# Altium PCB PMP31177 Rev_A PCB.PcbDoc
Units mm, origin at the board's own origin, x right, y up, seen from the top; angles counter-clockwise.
Board outline 38.73 x 19.68 mm, 4 copper layers (Top Layer, Layer 1, Layer 2, Bottom Layer), stack 1.787 mm thick; 35 components, 19 nets, 80 pads, 40 vias.
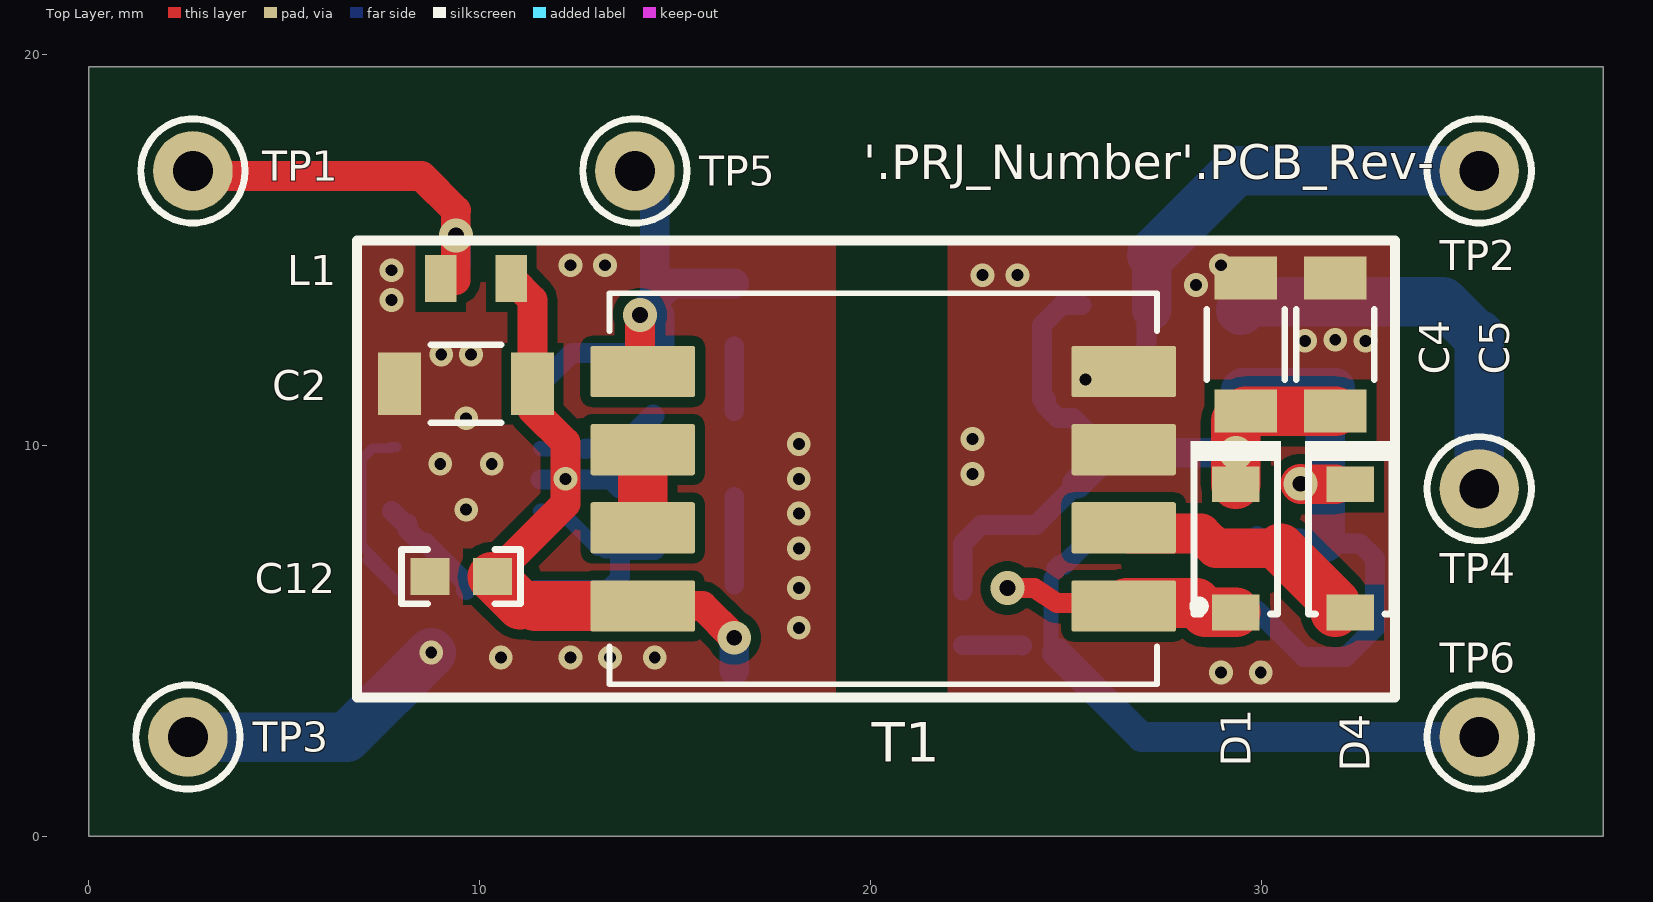
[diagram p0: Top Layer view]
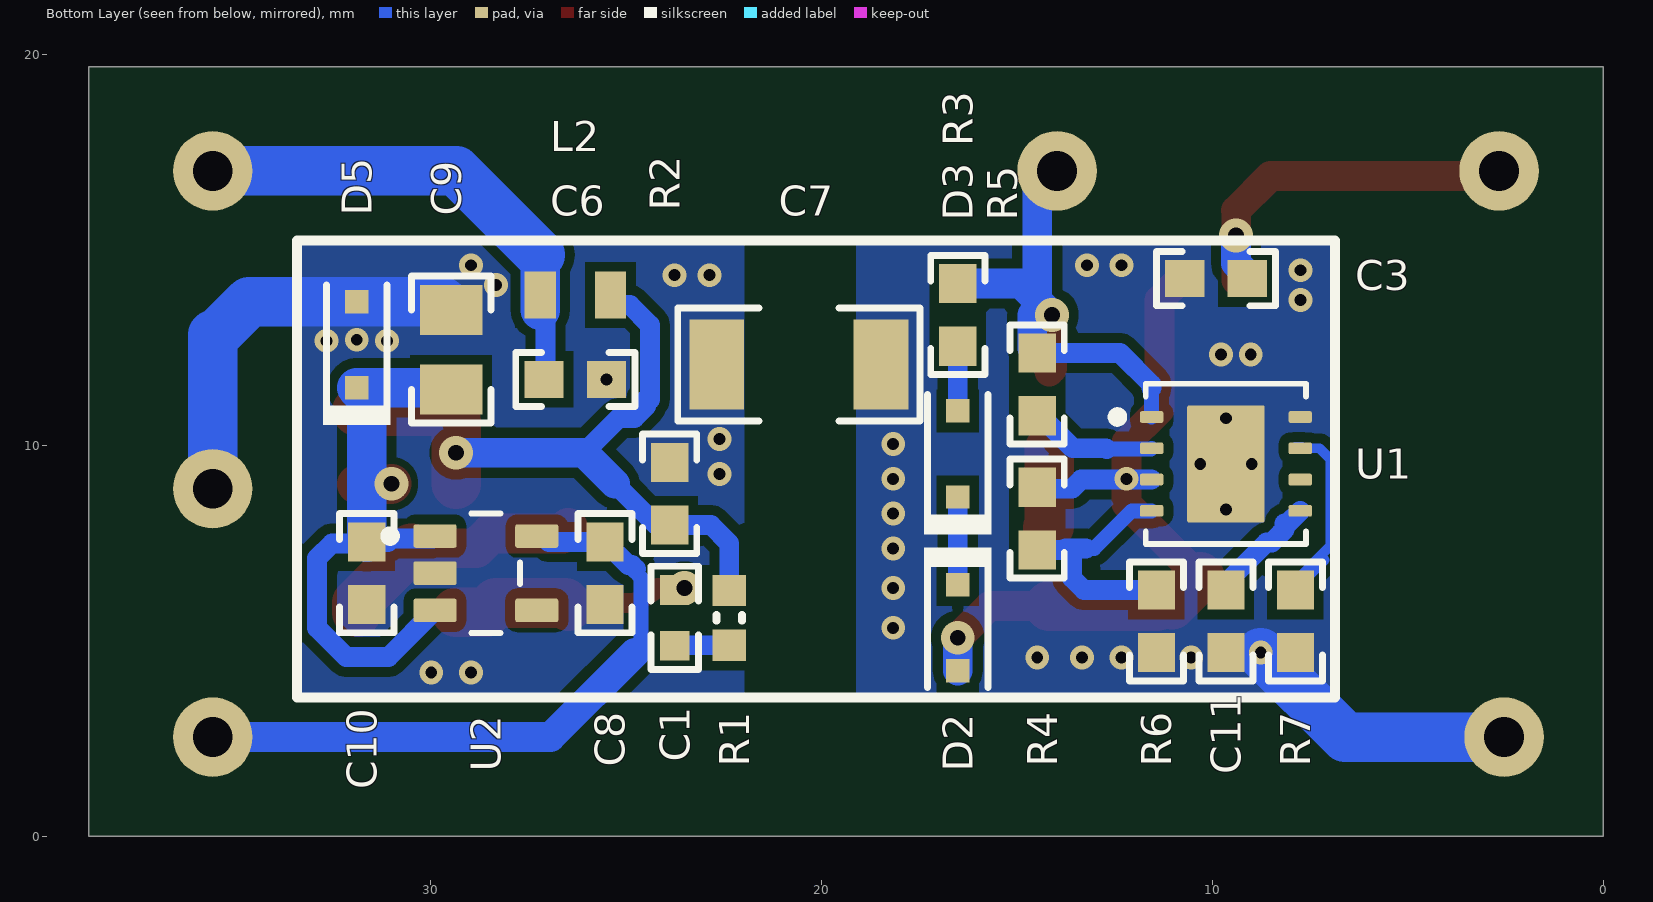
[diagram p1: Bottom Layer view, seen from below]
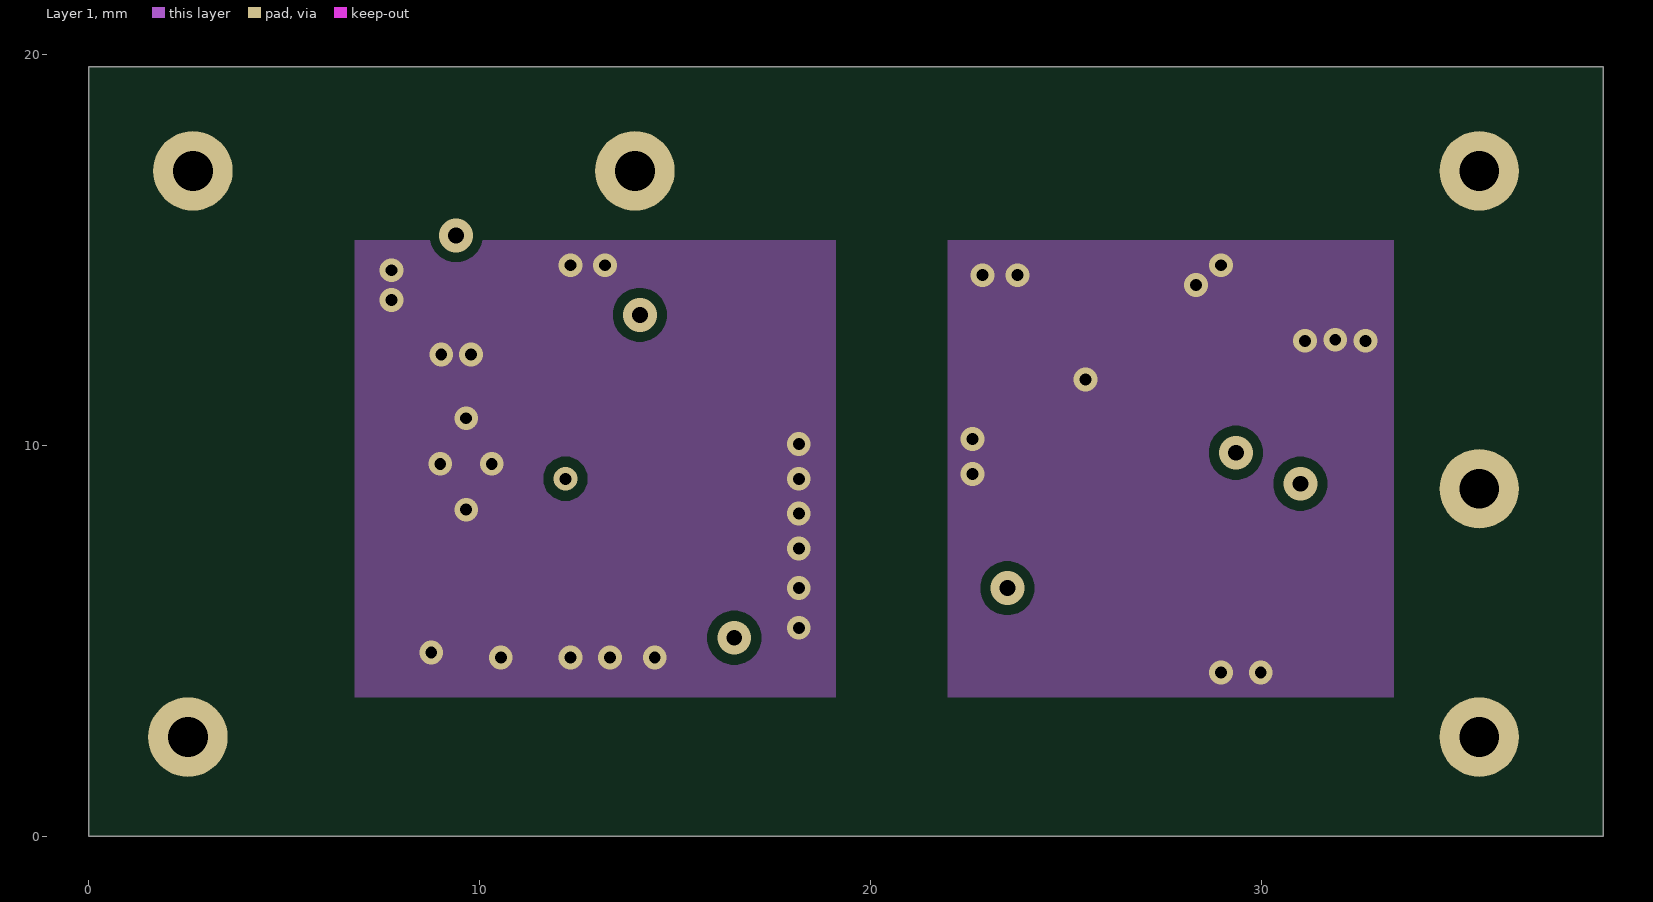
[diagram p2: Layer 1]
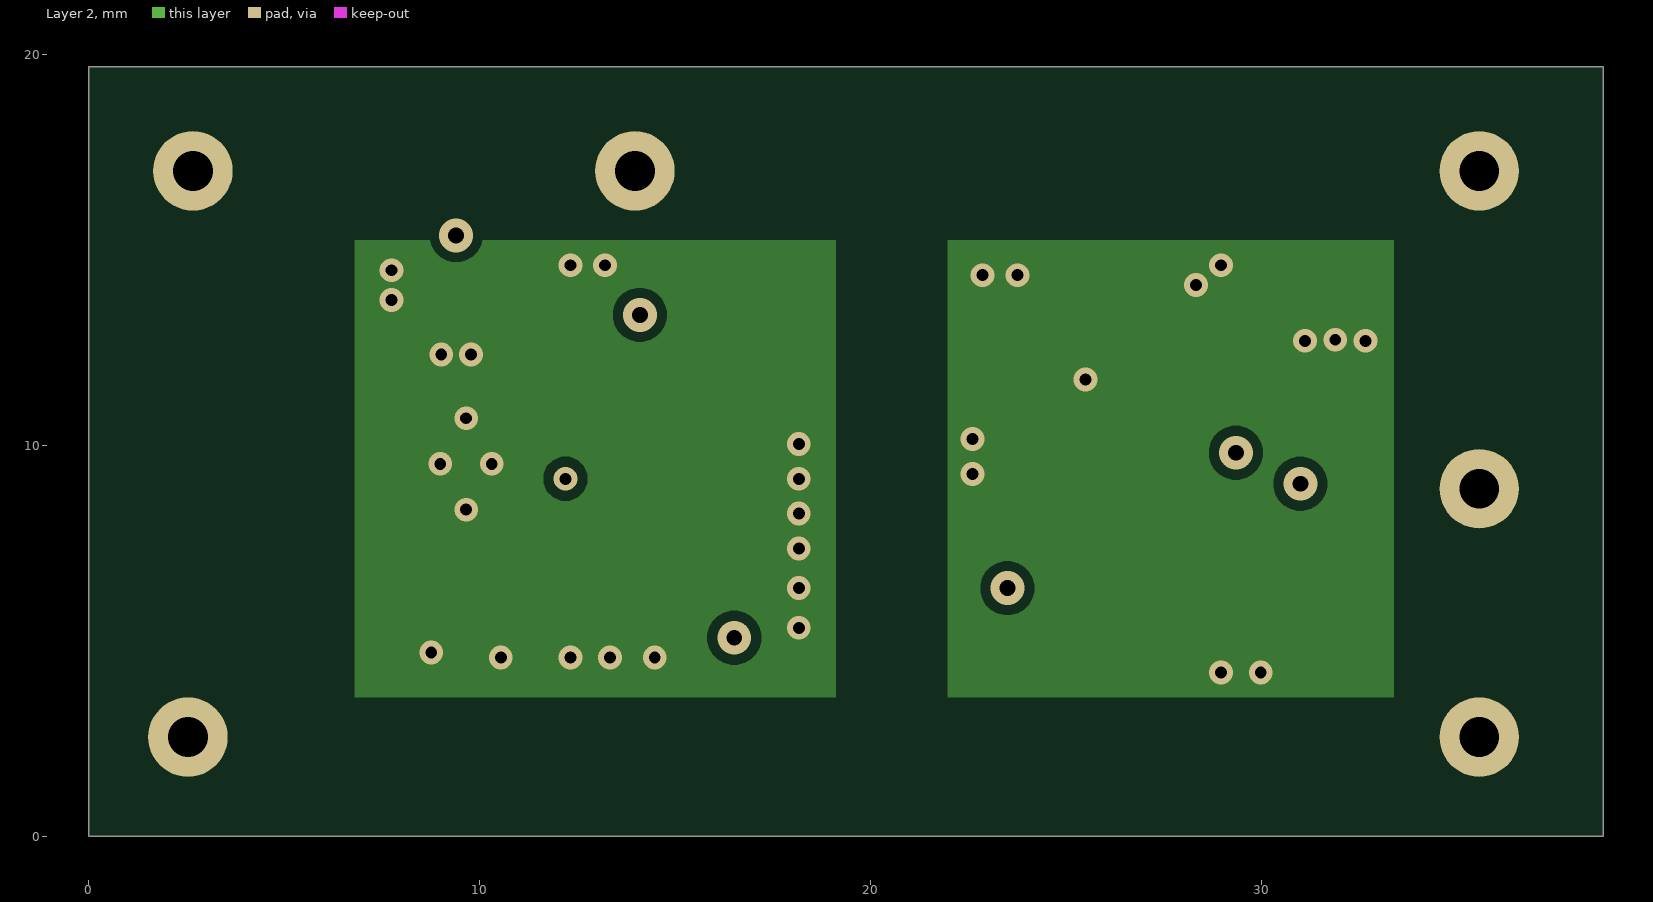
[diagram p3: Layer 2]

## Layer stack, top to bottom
Top Solder: solder mask 0.0102, Solder Resist, Dk 3.5
Top Layer: signal copper 0.0356
Dielectric 1: prepreg 0.0711, PP-006, Dk 4.1
Layer 1: signal copper 0.035
Dielectric1: core 1.5037, FR-4, Dk 4.8
Layer 2: signal copper 0.035
Dielectric 2: prepreg 0.0711, PP-006, Dk 4.1
Bottom Layer: signal copper 0.0356
Bottom Solder: solder mask 0.0102, Solder Resist, Dk 3.5

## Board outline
0,0 0,19.685 38.735,19.685 38.735,0

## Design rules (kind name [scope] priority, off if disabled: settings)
AcuteAngle [All] p1: minimum=4.50000000000000E+0001 checktracksonly=FALSE
AssemblyTestPointUsage [All] p1: valid=2
BoardOutlineClearance BoardOutlineClearance_MountingHoles [OnCopper and InComponentClass('Mounting Holes')] p1: gap=1.016 ignorepadtopadclearanceinfootprint=FALSE
BoardOutlineClearance BoardOutlineClearance_Poly [OnCopper and IsPoly] p2: gap=0.635 ignorepadtopadclearanceinfootprint=FALSE
BoardOutlineClearance [OnCopper and Not InComponentClass('Logo') and not InComponentClass('FiducialMark') and not InRegion(1000,500,4000,800) and not InPoly] p3: gap=1.905 ignorepadtopadclearanceinfootprint=FALSE
Clearance Clearance_1 [All] p1: gap=0.254 ignorepadtopadclearanceinfootprint=FALSE except(0: Arc-Hole Track-Hole SMDPad-Hole THPad-Hole Via-Hole Fill-Hole Poly-Hole Region-Hole Text-Hole)
Clearance Clearance_Keepouts [((IsTrack Or IsArc) And Not InPoly) And IsFree and IsKeepOut vs ((IsTrack Or IsArc) And Not InPoly) And IsFree and IsKeepOut] p2: gap=0 ignorepadtopadclearanceinfootprint=FALSE
Clearance Clearance_Poly [InPolygon] p3: gap=0.254 ignorepadtopadclearanceinfootprint=FALSE
Clearance Clearance_FiducialMark [IsKeepOut and InComponentClass('FiducialMark') vs IsPad and InComponentClass('FiducialMark')] p4: gap=0 ignorepadtopadclearanceinfootprint=FALSE
Clearance [All] p5: gap=0.254 ignorepadtopadclearanceinfootprint=FALSE
ComponentClearance ComponentClearance_MountingHoles_FiducialMarks [InComponentClass('Mounting Holes') vs InComponentClass('FiducialMark')] p1: gap=1.27 collisioncheckmode=3 verticalgap=0.254 showdistances=FALSE
ComponentClearance ComponentClearance_Shunt [InComponentClass('Header') vs InComponentClass('Shunt')] p2: gap=0 collisioncheckmode=3 verticalgap=0 showdistances=FALSE
ComponentClearance ComponentClearance_Logo [InComponentClass('Logo')] p3: gap=1.27 collisioncheckmode=3 verticalgap=0.254 showdistances=FALSE
ComponentClearance ComponentClearance_ScrewToNut [(HasFootprint('NY PMS 440 0025 PH')) vs (HasFootprint('Keystone_1902C'))] p4: gap=0.127 collisioncheckmode=3 verticalgap=0.254 showdistances=FALSE
ComponentClearance ComponentClearance_MountingHoles [InComponentClass('Mounting Holes')] p5: gap=6.35 collisioncheckmode=3 verticalgap=2540 showdistances=FALSE
ComponentClearance ComponentClearance_SmallPassives [HasFootprint('0201*') or HasFootprint('0402*') or HasFootprint('0508') or HasFootprint('0603*') or HasFootprint('0612') or HasFootprint('0805*') or HasFootprint('0815*') or HasFootprint('0830*') or HasFootprint('1206*') or HasFootprint('1210*') or HasFootprint('1808*') or HasFootprint('1812*') or HasFootprint('1825*') or HasFootprint('2010*') or HasFootprint('2220*') or HasFootprint('2225*') or HasFootprint('2512*') or HasFootprint('2728*') or HasFootprint('3518*') vs HasFootprint('0201*') or HasFootprint('0402*') or HasFootprint('0508') or HasFootprint('0603*') or HasFootprint('0612') or HasFootprint('0805*') or HasFootprint('0815*') or HasFootprint('0830*') or HasFootprint('1206*') or HasFootprint('1210*') or HasFootprint('1808*') or HasFootprint('1812*') or HasFootprint('1825*') or HasFootprint('2010*') or HasFootprint('2220*') or HasFootprint('2225*') or HasFootprint('2512*') or HasFootprint('2728*') or HasFootprint('3518*')] p6: gap=0.38 collisioncheckmode=3 verticalgap=0.254 showdistances=FALSE
ComponentClearance ComponentClearance_THtoSMT [IsThruComponent vs IsSMTComponent] p7: gap=1.016 collisioncheckmode=3 verticalgap=0.762 showdistances=FALSE
ComponentClearance ComponentClearance_THtoTH [IsThruComponent vs IsThruComponent] p8: gap=0.762 collisioncheckmode=3 verticalgap=0.762 showdistances=FALSE
ComponentClearance [All] p9: gap=0.762 collisioncheckmode=3 verticalgap=0.254 showdistances=FALSE
DiffPairsRouting [All] p1: maxlimit=2.54 minlimit=0.254 mostfreqgap=0.254 toplayer_minwidth=0.381 toplayer_maxwidth=0.381 toplayer_prefwidth=0.381 midlayer1_minwidth=0.381 midlayer1_maxwidth=0.381 midlayer1_prefwidth=0.381 midlayer2_minwidth=0.381 midlayer2_maxwidth=0.381 midlayer2_prefwidth=0.381 bottomlayer_minwidth=0.381 bottomlayer_maxwidth=0.381 bottomlayer_prefwidth=0.381 maxuncoupledlength=25.4
FabricationTestPointUsage TestPointUsage [All] p1: valid=2 allowmultiple=FALSE
FabricationTestpoint Testpoint [All] p1: side=3 testpointundercomponent=TRUE minsize=1.016 maxsize=2.54 preferedsize=1.524 minholesize=0 maxholesize=1.016 preferedholesize=0.813 testpointgrid=0.025 allowsidetop=TRUE allowsidebottom=TRUE usegrid=TRUE gridtolerance=0
FanoutControl Fanout_LCC [IsLCC] p1: bgadir=Out bgaviamode=Centered fanoutstyle=Auto fanoutdirection=Alternating viagrid=0.025 // Fanout_LCC (Default Rule)
FanoutControl Fanout_BGA [IsBGA] p2: bgadir=Out bgaviamode=Centered fanoutstyle=Auto fanoutdirection=Alternating viagrid=0.025 // Fanout_BGA (Default Rule)
FanoutControl Fanout_Default [All] p4: bgadir=Out bgaviamode=Centered fanoutstyle=Auto fanoutdirection=Alternating viagrid=0.025 // Fanout_Default (Default Rule)
FanoutControl Fanout_Small [(CompPinCount < 5)] p5: bgadir=Out bgaviamode=Centered fanoutstyle=Auto fanoutdirection=OutThenIn viagrid=0.025 // Fanout_Small (Default Rule)
HoleSize [All] p1: absolutevalues=TRUE maxlimit=6.375 minlimit=0.3 maxpercent=80.000 minpercent=20.000
MinimumAnnularRing MinimumAnnularRing_ThermalPadVias [IsVia and InAnyComponent] p1: minimumring=0.15
MinimumAnnularRing [All] p2: minimumring=0.152
MinimumSolderMaskSliver MinimumSolderMaskSliver_Logo [InComponentClass('Logo') vs InComponentClass('Logo')] p1: minsoldermaskwidth=0.018
MinimumSolderMaskSliver [All] p2: minsoldermaskwidth=0.1
PlaneConnect [All] p1: planeconnectstyle=Relief reliefexpansion=0.254 reliefentries=4 reliefconductorwidth=0.254 reliefairgap=0.254
PolygonConnect PolygonConnect_8 [All vs IsNamedPolygon('BOTTOM_LAYER_GND_P004')] p1: connectstyle=Direct reliefconductorwidth=0.254 reliefentries=4 polygonreliefangle="90 Angle" airgapwidth=0.254
PolygonConnect PolygonConnect_7 [All vs IsNamedPolygon('LAYER_2_GND_P007')] p2: connectstyle=Direct reliefconductorwidth=0.254 reliefentries=4 polygonreliefangle="90 Angle" airgapwidth=0.254
PolygonConnect PolygonConnect_6 [All vs IsNamedPolygon('LAYER_1_GND_P006')] p3: connectstyle=Direct reliefconductorwidth=0.254 reliefentries=4 polygonreliefangle="90 Angle" airgapwidth=0.254
PolygonConnect PolygonConnect_5 [All vs IsNamedPolygon('TOP_LAYER_GND_P005')] p4: connectstyle=Direct reliefconductorwidth=0.254 reliefentries=4 polygonreliefangle="90 Angle" airgapwidth=0.254
PolygonConnect PolygonConnect_4 [All vs IsNamedPolygon('LAYER_2_SGND_P003')] p5: connectstyle=Direct reliefconductorwidth=0.254 reliefentries=4 polygonreliefangle="90 Angle" airgapwidth=0.254
PolygonConnect PolygonConnect_3 [All vs IsNamedPolygon('LAYER_1_SGND_P002')] p6: connectstyle=Direct reliefconductorwidth=0.254 reliefentries=4 polygonreliefangle="90 Angle" airgapwidth=0.254
PolygonConnect PolygonConnect_2 [All vs IsNamedPolygon('TOP_LAYER_SGND_P001')] p7: connectstyle=Direct reliefconductorwidth=0.254 reliefentries=4 polygonreliefangle="90 Angle" airgapwidth=0.254
PolygonConnect PolygonConnect_1 [All vs IsNamedPolygon('BOTTOM_LAYER_SGND_P000')] p8: connectstyle=Direct reliefconductorwidth=0.254 reliefentries=4 polygonreliefangle="90 Angle" airgapwidth=0.254
PolygonConnect [All] p9: connectstyle=Relief reliefconductorwidth=0.254 reliefentries=4 polygonreliefangle="90 Angle" airgapwidth=0.254
RoutingVias ThermalPadVias [IsVia and InAnyComponent] p1: holewidth=0.2 width=0.5 viastyle="Through Hole" minholewidth=0.2 minwidth=0.5 maxholewidth=0.33 maxwidth=0.6
RoutingVias [All] p2: holewidth=0.406 width=0.864 viastyle="Through Hole" minholewidth=0.3 minwidth=0.6 maxholewidth=1.016 maxwidth=1.651
SilkToBoardRegionClearance [Not ((IsComment or IsDesignator) And (Hide <> 'False')) and not InRegion(1000,500,4000,800)] p1:
SilkToSilkClearance SilkToSilkClearance_Pb-FreeLogo [(HasFootprint('Pb-Free_Overlay_Medium') OR HasFootprint('Pb-Free_Overlay_Small')) vs (HasFootprint('Pb-Free_Overlay_Medium') OR HasFootprint('Pb-Free_Overlay_Small'))] p1: silktosilkclearance=0
SilkToSilkClearance [All] p2: silktosilkclearance=0.102
SilkToSolderMaskClearance SilkToComponentPadClearance [(IsPad or IsFill or IsRegion) and InAnycomponent] p1: minsilkscreentomaskgap=0.127 clearancetoexposedcopper=TRUE
SilkToSolderMaskClearance "Silk to Solder Mask Opening" [All] p2: minsilkscreentomaskgap=0.102 clearancetoexposedcopper=FALSE
SolderMaskExpansion [All] p1: expansion=0.05 istentingtop=FALSE
Width [All] p1: maxlimit=2.54 minlimit=0.152 preferedwidth=0.254 checkconnectedcopper=TRUE
15 further rules are at their usual default settings.

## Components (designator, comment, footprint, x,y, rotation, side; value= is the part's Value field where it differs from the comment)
C1 "GRM1885C2A220JA01D" 0603_HV 23.749,5.588 r90 bottom value=DNP
C2 "GRM31CR71H475KA12L" 1206_180 9.652,11.575 r180 top value=4.7uF
C3 "0603BB104KW101" 0603 9.906,14.262 r0 bottom value=0.1uF
C4 "GRM31CR71H475KA12L" 1206_180 29.591,12.573 r90 top value=4.7uF
C5 "GRM31CR71H475KA12L" 1206_180 31.877,12.573 r90 top value=4.7uF
C6 "0603BB104KW101" 0603 26.289,11.684 r180 bottom value=0.1uF
C7 "502R29W471KV3E" 1808 20.574,12.065 r180 bottom value=470pF
C8 "CGJ3E1X7R1E105K080AC" 0603 25.527,6.731 r270 bottom value=1uF
C9 "GRM21BR61A226ME44L" 0805_HV 29.464,12.446 r90 bottom value=22uF
C10 "CGJ3E1X7R1E105K080AC" 0603 31.623,6.731 r270 bottom value=1uF
C11 "GRM188R71E473KA01D" 0603 9.652,5.499 r270 bottom value=0.047uF
C12 "0603BB104KW101" 0603 9.525,6.642 r180 top value=0.1uF
D1 "DSS115U" SOD-123FL 29.337,7.366 r270 top
D2 "MMSZ5252BS-7-F" SOD-323 16.51,5.334 r270 bottom value=24V
D3 "1N4148WS-7-F" SOD-323 16.51,9.779 r90 bottom value=75V
D4 "DSS16U" SOD-123FL 32.258,7.366 r270 top
D5 "BZT52C5V1S-7-F" SOD-323 31.877,12.573 r90 bottom value=5.1V
L1 "MPZ2012S601AT000" MPZ2012 9.906,14.262 r0 top value="600 ohm @ 100 MHz"
L2 "MPZ2012S601AT000" MPZ2012 26.289,13.843 r0 bottom value="600 ohm @ 100 MHz"
R1 "CRCW0603100RFKEA" 0603L 22.352,5.588 r270 bottom value=DNP
R2 "RC0603FR-0756K2L" 0603 23.876,8.763 r270 bottom value=56.2k
R3 "RC0603FR-0710RL" 0603 16.51,13.335 r270 bottom value=10.0
R4 "RT0603DRE0786K6L" 0603 14.478,8.128 r90 bottom value=86.6k
R5 "RC0603FR-07147KL" 0603 14.478,11.557 r90 bottom value=147k
R6 "RC0603FR-078K45L" 0603 11.43,5.499 r90 bottom value=8.45k
R7 "RC0603FR-0712K1L" 0603 7.874,5.499 r90 bottom value=12.1k
T1 "750320139r00" FP-750320139r00_SMT_TRANSFORMER_14MM00_10MM00-MFG 20.32,8.89 r180 top
TP1 "5000" Keystone5000 2.667,17.018 r0 top
TP2 "5000" Keystone5000 35.56,17.018 r90 top
TP3 "5001" Keystone5001 2.54,2.54 r90 top
TP4 "5001" Keystone5001 35.56,8.89 r90 top
TP5 "5003" Keystone5003 13.97,17.018 r90 top
TP6 "5003" Keystone5003 35.56,2.54 r90 top
U1 "LM5181NGUR" NGU0008C-MFG 9.652,9.525 r180 bottom
U2 "TPS7A2033PDBVR" DBV0005A-MFG 28.575,6.731 r180 bottom

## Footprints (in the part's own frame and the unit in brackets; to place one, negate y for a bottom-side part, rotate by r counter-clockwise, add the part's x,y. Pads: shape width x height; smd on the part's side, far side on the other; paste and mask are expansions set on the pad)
0603 [mm] "0603 from SM-752 data"
  rect 1x0.95 smd: 1(-0.8,0) 2(0.8,0)
  silkscreen extent -1.52,-0.69 1.52,0.69, body extent -0.87,-0.47 0.87,0.47, height 1
0603_HV [mil] "Ernesto recommended land pattern.  26 mil between pads."
  rect 30x30 smd: 1(-28,0) 2(28,0)
  silkscreen extent -52,-24 52,24, body extent -34,-19 34,19, height 39
0603L [mm] "0603 from SM-752 data"
  rect 0.8x0.85 smd: 1(-0.7,0) 2(0.7,0)
  silkscreen extent -0.07,-0.33 0.07,0.33, body extent -0.87,-0.47 0.87,0.47, height 1
0805_HV [mil] "0805 with 30mil clearance between pads"
  rect 50x63 smd: 1(-40,0) 2(40,0)
  silkscreen extent -74,-40 74,40, body extent -43,-29 43,29, height 57
1206_180 [mm] "1206_180"
  rect 1.1x1.6 smd: 1(-1.7,0) 2(1.7,0)
  silkscreen extent -0.9,-1 0.9,1, body extent -1.75,-0.95 1.75,0.95, height 1.8
1808 [mm] "Chip Capacitor, Body 4.6x2.0mm, IPC Medium Density"
  rect 1.4x2.3 smd: 1(-2.1,0) 2(2.1,0)
  silkscreen extent -3.1,-1.45 3.1,1.45, body extent -2.47,-1.2 2.47,1.2, height 2.03
DBV0005A-MFG [mm]
  rrect17% 1.1x0.6 smd paste+0 mask+0: 1(-1.3,0.95) 2(-1.3,0) 3(-1.3,-0.95) 4(1.3,-0.95) 5(1.3,0.95)
  silkscreen extent -2.58,-1.53 0.87,1.53, body extent -1.4,-1.45 1.4,1.45, height 1.45
FP-750320139r00_SMT_TRANSFORMER_14MM00_10MM00-MFG [mm]
  rrect8% 2.67x1.31 smd paste+0 mask+0: 1(-6.15,3) 2(-6.15,1) 3(-6.15,-1) 4(-6.15,-3) 5(6.15,-3) 6(6.15,-1) 7(6.15,1) 8(6.15,3)
  silkscreen extent -8.2,-5 7,5, body extent -7.58,-5.1 7.58,5.1, height 0.25
Keystone5000 [mil] "For Keystone 500x miniature loop terminals"
  round 80 hole 40: 1(0,0)
  silkscreen extent -52,-52 52,52, body extent -49,-49 49,49, height 182
Keystone5001 [mil] "For Keystone 500x miniature loop terminals"
  round 80 hole 40: 1(0,0)
  silkscreen extent -52,-52 52,52, body extent -49,-49 49,49, height 182
Keystone5003 [mil] "For Keystone 500x miniature loop terminals"
  round 80 hole 40: 1(0,0)
  silkscreen extent -52,-52 52,52, body extent -49,-49 49,49, height 182
MPZ2012 [mm] "TDK"
  rect 0.8x1.2 smd: 1(-0.9,0) 2(0.9,0)
  body extent -1.1,-0.72 1.1,0.72, height 1.05
NGU0008C-MFG [mm]
  rrect33% 0.6x0.3 smd paste+0 mask+0: 1(-1.9,1.2) 2(-1.9,0.4) 3(-1.9,-0.4) 4(-1.9,-1.2) 5(1.9,-1.2) 6(1.9,-0.4) 7(1.9,0.4) 8(1.9,1.2)
  rrect5% 1.98x3 smd paste-1000 mask+0: 9(0,0)
  silkscreen extent -2.9,-2.05 2.05,2.05, body extent -2,-2 2,2, height 0.8
SOD-123FL [mm] "Copied from SOD-123"
  rect 0.915x1.22 smd: 1(-1.637,0) 2(1.637,0)
  silkscreen extent -2.74,-1.16 1.68,1.16, body extent -1.9,-0.9 1.9,0.9, height 1
SOD-323 [mm] "NXP recommended land pattern"
  rect 0.6x0.6 smd paste-0.05: 1(-1.1,0) 2(1.1,0)
  silkscreen extent -2.06,-0.86 1.53,0.86, body extent -1.3,-0.67 1.3,0.68, height 1.1

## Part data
C1: library part CMP-0007255-4, "DNP", Cap_Case=0603, Manufacturer=N/A
C2 C4 C5: library part CMP-0088282-2, "4.7µF ±10% 50V Ceramic Capacitor X7R 1206 (3216 Metric)", Cap_Case=2220, Manufacturer=MuRata, Supplier Part Number 1=24R6347, TempCo=X7R, Tolerance_%=10%, Value1=Unknown, Value2=50V, ValueDisplayed=4.7uF
C3 C6 C12: library part CMP-0860985-1, "CAP, CERM, 0.1 µF, 100 V,+/- 10%, X7R, 0603", Cap_Case=0603, Manufacturer="Passive Plus", TempCo=X7R, Tolerance_%=10%, Value2=100V, ValueDisplayed=0.1µF
C7: library part CMP-0009436-2, "CAP, CERM, 1000 pF, 2000 V, +/- 10%, X7R, 1808", Cap_Case=1808, Manufacturer="Johanson Dielectrics Inc.", Supplier Part Number 1=709-1267-2-ND, TempCo=X7R, Tolerance_%=10%, Value1="X1, Y2", Value2=500V, ValueDisplayed=470pF
C8 C10: library part CMP-0006833-4, "CAP, CERM, 1 uF, 25 V, +/- 10%, X7R, 0603", Cap_Case=0603, Manufacturer=TDK, TempCo=X7R, Tolerance_%=10%, Value2=25V, ValueDisplayed=1µF
C9: library part CMP-0078153-1, "CAP, CERM, 22 µF, 10 V,+/- 20%, X5R, 0805", Cap_Case=0805, Manufacturer=MuRata, Supplier Part Number 1=490-10746-1-ND, TempCo=X5R, Tolerance_%=20%, Value1=Unknown, Value2=10V, ValueDisplayed=22uF
C11: library part CMP-0086483-1, "0.047µF ±10% 25V Ceramic Capacitor X7R 0603 (1608 Metric)", Cap_Case=0603, Manufacturer=MuRata, Supplier Part Number 1=490-1522-1-ND, TempCo=X7R, Tolerance_%=10%, Value1=Unknown, Value2=25V, ValueDisplayed=0.047uF
D1: library part CMP-0028776-1, "Diode, Schottky, 150 V, 1 A, SOD-123FL", Manufacturer="SMC Diode Solutions", Supplier Part Number 1=1655-DSS115UTR-ND, Value1=1A, Value2=0.94V
D2: library part CMP-0005838-4, "Diode, Zener, 24 V, 200 mW, SOD-323", Manufacturer="Diodes Inc.", Power_W=200mW, Value1=0.2W
D3: library part CMP-0079597-2, "Diode, Switching, 75 V, 0.15 A, AEC-Q101, SOD-323", Manufacturer="Diodes Inc.", Value1=0.15A, Value2=1.25V
D4: library part CMP-0028776-1, "Diode, Schottky, 60 V, 1 A, SOD-123FL", Manufacturer="SMC Diode Solutions", Supplier Part Number 1=1655-DSS16UTR-ND, Value1=1A, Value2=0.94V
D5: library part CMP-0005865-3, "Diode, Zener, 5.1 V, 200 mW, SOD-323", Manufacturer="Diodes Inc.", Power_W=200mW, Value1=0.2W
L1 L2: library part CMP-0003136-1, "Ferrite Bead, 600 ohm @ 100 MHz, 2.1 A, 0805", Manufacturer=TDK, Supplier Part Number 1=445-2206-1-ND, Value1="0.1 ohm", Value2=2A, ValueDisplayed="600 ohm"
R1: library part CMP-0021991-3, "DNP", Manufacturer=N/A
R2: library part CMP-0023186-5, "RES, 56.2 k, 1%, 0.1 W, 0603", Manufacturer=Yageo, Power_W=100mW, Supplier Part Number 1=311-56.2KHRCT-ND, TempCo="100 ppm/C", Tolerance_%=1%, Value2=0.1W, Value_Code=56k2, ValueDisplayed=56.2k
R3: library part CMP-0022751-4, "RES, 10.0, 1%, 0.1 W, 0603", Manufacturer=Yageo, Power_W=100mW, Supplier Part Number 1=311-10.0HRCT-ND, TempCo="100 ppm/C", Tolerance_%=1%, Value2=0.1W, Value_Code=10R0, ValueDisplayed=10.0
R4: library part CMP-0025613-3, "RES, 86.6 k, 0.5%, 0.1 W, 0603", Manufacturer="Yageo America", Power_W=100mW, TempCo="50 ppm/C", Tolerance_%=0.5%, Value2=0.1W, Value_Code=86k6, ValueDisplayed=86.6k
R5: library part CMP-0022798-4, "RES, 143 k, 1%, 0.1 W, 0603", Manufacturer=Yageo, Power_W=100mW, Supplier Part Number 1=311-147KHRCT-ND, TempCo="100 ppm/C", Tolerance_%=1%, Value2=0.1W, Value_Code=147k
R6: library part CMP-0023309-5, "RES, 8.45 k, 1%, 0.1 W, 0603", Manufacturer=Yageo, Power_W=100mW, Supplier Part Number 1=311-8.45KHRCT-ND, TempCo="100 ppm/C", Tolerance_%=1%, Value2=0.1W, Value_Code=8k45, ValueDisplayed=8.45k
R7: library part CMP-0022776-5, "RES, 12.1 k, 1%, 0.1 W, 0603", Manufacturer=Yageo, Power_W=100mW, Supplier Part Number 1=311-12.1KHRCT-ND, TempCo="100 ppm/C", Tolerance_%=1%, Value2=0.1W, Value_Code=12k1, ValueDisplayed=12.1k
T1: library part CMP-0095946-1, "TRANSFORMER", Frequency_Fixed=350kHz, Manufacturer=Wurth, Operating Temperature Range="-40°C to +125°C", Voltage_Isolation_Vrms=1.6kV
TP1 TP2: library part CMP-0055137-2, "Test Point, Miniature, Red, TH", Color=Red, Manufacturer="Keystone Electronics", Supplier Part Number 1=36-5000-ND
TP3 TP4: library part CMP-0055138-2, "Test Point, Miniature, Black, TH", Color=Black, Manufacturer="Keystone Electronics", Supplier Part Number 1=36-5001-ND
TP5 TP6: library part CMP-0055140-2, "Test Point, Miniature, Orange, TH", Color=Orange, Manufacturer="Keystone Electronics", Supplier Part Number 1=36-5003-ND
U1: library part CMP-0088992-1, "65-VIN PSR Flyback DC/DC Converter with 100-V, 0.75-A Integrated MOSFET", Manufacturer="Texas Instruments", Max Supply Voltage=65V, Min Supply Voltage=4.5V, Nominal Supply Current=25-260uA, Operating Temperature Range="-40°C to +150°C", Switching Frequency=350kHz
U2: library part CMP-0092532-1, "300-mA, Ultra-Low-Noise, Low-IQ, High PSRR LDO", Digikey Part Number=296-TPS7A2033PDBVRCT-ND, Dropout Voltage=145mV, Manufacturer="Texas Instruments", Max Supply Voltage=6V, Min Supply Voltage=1.6V, Mouser Part Number=595-TPS7A2033PDBVR, Nominal Supply Current=6.5uA, Operating Temperature Range="-40°C to +125°C", Output Voltage=3.3V

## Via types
v1: diameter 0.61, hole 0.305, Top Layer to Bottom Layer, 29 vias
v2: diameter 0.864, hole 0.406, Top Layer to Bottom Layer, 6 vias
v3: diameter 0.6, hole 0.3, Top Layer to Bottom Layer, 4 vias
v4: diameter 0.61, hole 0.305, Top Layer to Bottom Layer, tented bottom, 1 vias

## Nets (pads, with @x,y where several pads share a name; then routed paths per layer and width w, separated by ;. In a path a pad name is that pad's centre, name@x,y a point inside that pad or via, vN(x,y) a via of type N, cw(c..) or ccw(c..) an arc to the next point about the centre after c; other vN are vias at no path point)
GND: C2.2 C3.2 C7.2 C11.2 C12.2 R6.1 R7.1 TP3.1 U1.8 U1.9 | length 7.1
  Bottom Layer w1.27: TP3.1 6.604,2.54 v1(8.763,4.699)
  other v1: 10.541,4.572 12.319,4.572 13.335,4.572 14.478,4.572 18.161,5.334 18.161,6.35 18.161,7.366 18.161,8.255 18.161,9.144 18.161,10.033 9.017,12.319 9.779,12.319 7.747,13.716 7.747,14.478 12.319,14.605 13.208,14.605
  other v3: 9.652,8.357 8.992,9.525 10.312,9.525 9.652,10.693
NetC1_1: C1.1 R1.2 | length 1.5
  Bottom Layer w0.508: R1.2 23.865,4.888 C1.1@23.876,4.877
NetC1_2: C1.2 D1.2 T1.1 | length 6.2
  Top Layer w0.508: v2(23.495,6.35) 24.181,6.35 24.765,5.969 26.391,5.969 T1.1 ; D1.2@29.337,5.69 D1.2
  Top Layer w1.27: T1.1 26.549,5.969 28.321,5.969 28.561,5.729 D1.2
NetC2_1: C2.1 C12.1 D2.2 L1.2 R4.2 T1.8 U1.3 | length 19.3
  Top Layer w0.762: C12.1 12.192,8.508 v4(12.192,9.144) 12.192,10.071 11.352,10.911 11.352,12.357 11.352,13.716 L1.2 ; T1.8 15.7,5.89 v2(16.51,5.08)
  Top Layer w1.27: C12.1 11.039,5.928 ; 11.42,5.89 T1.8
  Bottom Layer w0.508: U1.3 13.354,9.125 13.589,8.89 14.44,8.89 R4.2
  Bottom Layer w0.762: D2.2 v2(16.51,5.08)
NetC3_1: C3.1 L1.1 TP1.1 | length 10.6
  Top Layer w0.762: TP1.1 2.54,16.891 8.509,16.891 9.398,16.002 9.387,15.991 L1.1@9.387,14.224
  Bottom Layer w0.762: C3.1 9.006,14.262 9.398,14.654 v2(9.398,15.367)
NetC4_1: C4.1 C5.1 D1.1 L2.1 R1.1 R2.2 | length 18.9
  Top Layer w1.27: D1.1 v2(29.337,9.811) 29.337,10.619 C4.1 C5.1
  Bottom Layer w0.508: R1.1 22.352,7.493 22.822,7.963 R2.2 24.219,7.963 25.273,9.017 ; L2.1@25.389,13.589 24.892,13.589 24.384,13.081 24.384,11.176 24.481,11.176 24.481,10.999 24.645,10.835 24.779,10.701 25.178,10.701 26.067,9.811
  Bottom Layer w0.762: 25.273,9.017 26.067,9.811 v2(29.337,9.811)
NetC6_1: C6.1 L2.2 TP2.1 | length 12.6
  Bottom Layer w0.508: C6.1 27.089,11.9 27.051,11.938 27.051,13.451 L2.2@27.189,13.589
  Bottom Layer w1.016: L2.2@27.189,13.462 27.189,13.589 27.189,14.87
  Bottom Layer w1.27: 27.189,14.87 29.337,17.018 TP2.1
NetC8_1: C8.1 TP6.1 U2.5 | length 16.9
  Bottom Layer w0.381: 24.739,6.836 24.784,6.791 24.607,6.615 24.607,4.857 24.765,4.699
  Bottom Layer w0.508: 24.739,6.836 24.842,6.939 24.935,6.939 C8.1 26.962,7.531 27.112,7.681 U2.5
  Bottom Layer w0.762: 24.765,4.699 26.924,2.54 TP6.1
NetC9_1: C9.1 C10.1 D4.1 D5.1 U2.1 U2.3 | length 16.2
  Top Layer w1.016: v2(30.988,9.017) 31.002,9.003 D4.1@31.877,9.003
  Bottom Layer w0.508: U2.3 31.069,4.587 32.146,4.587 32.893,5.334 32.893,7.112 32.512,7.493 31.661,7.493 C10.1 31.077,7.531 30.988,7.62 29.936,7.62 U2.1
  Bottom Layer w1.016: C9.1 29.507,11.473 D5.1 31.623,11.219 31.623,9.017 ; C10.1 31.623,9.003
NetC11_1: C11.1 U1.5 | length 2.9
  Bottom Layer w0.508: U1.5 8.071,8.006 8.154,8.006 8.154,7.844 8.221,7.776 8.253,7.745 8.38,7.618 8.443,7.554 8.481,7.517 8.612,7.517 9.652,6.477 C11.1
NetD2_1: D2.1 D3.1 | length 2.2
  Bottom Layer w0.508: D2.1 D3.1
NetD3_2: D3.2 R3.2 | length 1.7
  Bottom Layer w0.508: D3.2 R3.2
NetD4_2: D4.2 T1.2 | length 6.4
  Top Layer w1.016: T1.2 26.613,7.747 28.448,7.747 28.829,7.366 30.48,7.366
  Top Layer w1.27: 30.48,7.366 31.877,5.969 D4.2@31.877,5.729
NetR3_1: R3.1 R5.2 T1.5 TP5.1 U1.1 | length 13.4
  Top Layer w0.508: TP5.1 TP5.1@14.17,16.818
  Top Layer w0.762: v2(14.097,13.335) 14.097,11.963 T1.5
  Bottom Layer w0.381: U1.1 11.557,11.467
  Bottom Layer w0.508: 11.557,11.467 11.557,11.557 12.357,12.357 R5.2
  Bottom Layer w0.762: v2(14.097,13.335) 14.897,14.135 R3.1 ; R5.2 14.605,12.484 14.605,13.335 14.478,13.462 TP5.1@14.478,17.018
NetR4_1: R4.1 R6.2 U1.4 | length 6.5
  Bottom Layer w0.381: U1.4 12.06,8.325 13.019,7.366 13.227,7.366
  Bottom Layer w0.508: R6.2 13.284,6.299 13.589,6.604 13.589,7.202 13.715,7.328 ; 13.227,7.366 13.753,7.366 13.715,7.328 ; R4.1 13.715,7.328
NetR5_1: R5.1 U1.2 | length 3.3
  Bottom Layer w0.381: U1.2 11.571,9.906 12.7,9.906
  Bottom Layer w0.508: 12.7,9.906 12.719,9.925 13.57,9.925 14.44,10.795 R5.1
NetR7_2: R7.2 U1.7 | length 5.8
  Bottom Layer w0.254: 7.125,7.073 R7.2@7.874,6.324 ; U1.7@7.707,9.963 U1.7@7.879,9.963 ; U1.7 7.258,9.925 6.985,9.652 6.976,7.432 7.874,6.534 R7.2@7.874,6.324 ; R7.2 R7.2@7.874,6.324
NetT1_6: T1.6 T1.7 | length 2.1
  Top Layer w0.762: T1.7 T1.7@14.208,7.89
  Top Layer w1.27: T1.6 14.17,7.928 T1.7@14.208,7.89
SGND: C4.2 C5.2 C6.2 C7.1 C8.2 C9.2 C10.2 D5.2 R2.1 T1.3 T1.4 TP4.1 U2.2 | length 10.6
  Bottom Layer w0.508: C8.2 C8.2@25.616,5.931
  Bottom Layer w1.27: C9.2 29.675,13.673 D5.2 34.628,13.673 35.474,12.827 35.56,12.827 TP4.1
  other v1: 28.956,4.191 29.972,4.191 22.606,9.271 22.606,10.16 25.489,11.684 31.102,12.673 32.652,12.673 31.877,12.7 28.321,14.097 22.86,14.351 23.749,14.351 28.956,14.605
pads on no net: U1.6 U2.4

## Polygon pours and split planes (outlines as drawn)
GND on Bottom Layer "BOTTOM_LAYER_GND_P004" (solid, pour order 4): 6.807,15.24 19.101,15.24 19.101,3.556 6.807,3.556
SGND on Bottom Layer "BOTTOM_LAYER_SGND_P000" (solid, pour order 0): 21.971,15.24 33.376,15.24 33.376,3.556 21.971,3.556
GND on Top Layer "TOP_LAYER_GND_P005" (solid, pour order 5): 6.807,15.24 19.101,15.24 19.101,3.556 6.807,3.556
SGND on Top Layer "TOP_LAYER_SGND_P001" (solid, pour order 1): 21.971,15.24 33.376,15.24 33.376,3.556 21.971,3.556
GND on Layer 1 "LAYER_1_GND_P006" (solid, pour order 6): 6.807,15.24 19.101,15.24 19.101,3.556 6.807,3.556
SGND on Layer 1 "LAYER_1_SGND_P002" (solid, pour order 2): 21.971,15.24 33.376,15.24 33.376,3.556 21.971,3.556
GND on Layer 2 "LAYER_2_GND_P007" (solid, pour order 7): 6.807,15.24 19.101,15.24 19.101,3.556 6.807,3.556
SGND on Layer 2 "LAYER_2_SGND_P003" (solid, pour order 3): 21.971,15.24 33.376,15.24 33.376,3.556 21.971,3.556

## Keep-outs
Keep-Out Layer:
  text ".Layer_Name" at 14.656,-21.806 h1.52

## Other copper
Top Layer:
  text ".Layer_Name" at 14.656,-21.806 h1.52
Bottom Layer:
  text ".Layer_Name" at 14.656,-21.806 h1.52

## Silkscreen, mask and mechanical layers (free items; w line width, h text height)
Top Overlay:
  lines w0.254: 6.858,3.556 33.401,3.556 33.401,15.24 6.858,15.24 6.858,3.556
  text "'.PRJ_Number'.PCB_Rev-" at 19.812,16.51 h1.52
  text ".Layer_Name" at 14.656,-21.806 h1.52
Bottom Overlay:
  lines w0.254: 6.858,3.556 33.401,3.556 33.401,15.24 6.858,15.24 6.858,3.556
  text ".Layer_Name" at 14.656,-21.806 h1.52
Top Paste:
  text ".Layer_Name" at 14.656,-21.806 h1.52
Bottom Paste:
  text ".Layer_Name" at 14.656,-21.806 h1.52
Top Solder:
  text ".Layer_Name" at 14.656,-21.806 h1.52
  text ".Layer_Name" at 14.656,-21.806 h1.52
Bottom Solder:
  text ".Layer_Name" at 14.656,-21.806 h1.52
Drill Guide:
  text ".Layer_Name" at 14.656,-21.806 h1.52
M1 Board Outline:
  the board outline again, w0.254
  text ".Layer_Name" at 14.656,-21.806 h1.52
M2 Board Dimensions:
  rectangle: 0,-6.985 3.175,-3.81
  rectangle: 3.175,-10.16 12.7,-6.985
  lines w0.178: 0,-6.985 25.4,-6.985 ; 3.175,-10.16 3.175,-3.81 ; 6.35,-10.16 6.35,-3.81 ; 12.7,-10.16 12.7,-3.81 ; 19.05,-10.16 19.05,-3.81 ; 0,-10.16 25.4,-10.16 25.4,-3.81 0,-3.81 0,-10.16
  text ".Layer_Name" at 14.656,-21.806 h1.52
M3 3D STEP Top:
  text ".Layer_Name" at 14.656,-21.806 h1.52
M4 3D STEP Bottom:
  text ".Layer_Name" at 14.656,-21.806 h1.52
M5 Assembly Top:
  lines w0.254: -7.417,-23.626 160.223,-23.626 ; -7.417,-18.462 160.274,-18.462 ; -7.417,-13.297 -7.417,-28.791 94.31,-28.791 160.274,-28.791 160.274,-13.297 -7.404,-13.297 -7.404,-28.791 32.614,-28.791 ; 55.194,-28.791 55.194,-13.297 ; 87.376,-18.462 87.376,-13.297 ; 108.712,-18.462 108.712,-13.297 ; 124.511,-28.956 124.511,-23.804
  text "COMPONENTS MARKED 'DNP' SHOULD NOT BE POPULATED." at 29.299,-8.09 h1.52
  text "ASSEMBLY VARIANT:" at 29.286,-11.024 h1.52
  text ".VariantName" at 55.601,-11.024 h1.52
  text "PCB VIEWED FROM TOP SIDE" at -5.804,-16.654 h1.52
  text "BOARD #:" at 57.099,-16.654 h1.52
  text ".PRJ_Number" at 70.955,-16.654 h1.52
  text "REV:" at 92.405,-16.654 h1.52
  text ".PCB_Rev" at 99.809,-16.654 h1.52
  text "SVN REV:" at 113.69,-16.654 h1.52
  text ".VersionControl_RevNumber" at 126.543,-16.654 h1.52
  text "TID #:" at 57.099,-21.819 h1.52
  text ".TID" at 70.955,-21.819 h1.52
  text "PLOT NAME =" at -5.804,-27.034 h1.52
  text ".plot_File_Name" at 14.656,-27.034 h1.52
  text "GENERATED    :" at 57.15,-27.034 h1.52
  text ".Print_Date" at 79.235,-27.034 h1.52
  text ".Print_Time" at 97.752,-27.034 h1.52
  text "TEXAS INSTRUMENTS" at 129.87,-27.034 h1.52
M6 Assembly Bottom:
  lines w0.254: -7.429,-18.474 160.261,-18.474 ; -7.379,-23.639 160.261,-23.639 ; 28.334,-28.969 28.334,-23.817 ; 44.133,-18.474 44.133,-13.31 ; 65.468,-18.474 65.468,-13.31 ; 97.65,-28.804 97.65,-13.31 ; 120.231,-28.804 160.249,-28.804 160.249,-13.31 -7.429,-13.31 -7.429,-28.804 58.534,-28.804 160.261,-28.804 160.261,-13.31
  text "COMPONENTS MARKED 'DNP' SHOULD NOT BE POPULATED." at 154.991,-8.077 h1.52
  text ".VariantName" at 128.473,-11.024 h1.52
  text "ASSEMBLY VARIANT:" at 154.864,-11.024 h1.52
  text ".VersionControl_RevNumber" at 26.302,-16.667 h1.52
  text "SVN REV:" at 39.154,-16.667 h1.52
  text ".PCB_Rev" at 53.035,-16.667 h1.52
  text "REV:" at 60.439,-16.667 h1.52
  text ".PRJ_Number" at 81.89,-16.667 h1.52
  text "BOARD #:" at 95.745,-16.667 h1.52
  text "PCB VIEWED FROM BOTTOM SIDE" at 158.648,-16.667 h1.52
  text ".TID" at 81.89,-21.831 h1.52
  text "TID #:" at 95.745,-21.831 h1.52
  text "TEXAS INSTRUMENTS" at 22.974,-27.047 h1.52
  text ".Print_Time" at 55.093,-27.047 h1.52
  text ".Print_Date" at 73.609,-27.047 h1.52
  text "GENERATED    :" at 95.694,-27.047 h1.52
  text ".plot_File_Name" at 138.189,-27.047 h1.52
  text "PLOT NAME =" at 158.648,-27.047 h1.52
M9 Title Sheet:
  drawing of 57 lines, arcs and shapes, not listed
  text "1" at 18.792,204.127 h1.78
  text "2" at 82.182,204.127 h1.78
  text "3" at 145.411,204.127 h1.78
  text "4" at 209.08,204.127 h1.78
  text "5" at 272.555,204.127 h1.78
  text "6" at 336.182,204.127 h1.78
  text "A" at -10.579,175.095 h1.78
  text "A" at 365.341,175.095 h1.78
  text "B" at -10.579,114.643 h1.78
  text "B" at 365.341,114.643 h1.78
  text "C" at -10.579,54.318 h1.78
  text "C" at 365.341,54.318 h1.78
  text "PROJECT TITLE:" at 288.125,7.048 h1.14
  text ".PRJ_Title" at 289.395,3.662 h1.78
  text "DESIGNED FOR:" at 288.125,-0.597 h1.14
  text ".PRJ_Customer" at 289.395,-4.153 h1.78
  text "D" at -10.579,-5.88 h1.78
  text "D" at 365.341,-5.88 h1.78
  text "FILE NAME:" at 288.125,-8.217 h1.14
  text ".PCB_File_Name_No_Path" at 289.395,-11.265 h1.78
  text "Texas Instruments (TI) and/or its licensors do not warrant the accuracy or completeness of this specification" at 161.9,-15.376 h1.14
  text "ENGINEER:" at 288.125,-15.583 h1.14
  text "LAYOUT BY:" at 326.352,-15.583 h1.14
  text "or any information contained therein. TI and/or its licensors do not warrant that this design will meet" at 160.757,-18.237 h1.14
  text ".PRJ_Engineer" at 289.395,-19.52 h1.78
  text ".PCB_Layout" at 327.635,-19.52 h1.78
  text "the specifications, will be suitable for your application or fit for any particular purpose, or will operate in" at 160.757,-21.099 h1.14
  text ".Layer_Name" at 14.656,-21.806 h1.52
  text "ALTIUM DESIGNER VERSION:" at 326.352,-23.457 h1.14
  text "an implementation. TI and/or its licensors do not warrant that the design is production worthy. You should" at 160.757,-23.961 h1.14
  text "completely validate and test your design implementation to confirm the system functionality for your application." at 161.9,-26.822 h1.14
  text ".print_Scale" at 289.395,-26.843 h1.78
  text ".Application_BuildNumber" at 327.635,-26.843 h1.78
  text "1" at 18.792,-32.093 h1.78
  text "2" at 82.182,-32.093 h1.78
  text "3" at 145.411,-32.093 h1.78
  text "4" at 209.08,-32.093 h1.78
  text "5" at 272.555,-32.093 h1.78
  text "6" at 336.182,-32.093 h1.78
M10 Fab Notes:
  drawing of 189 lines, arcs and shapes, not listed
  text "DESIGN INFORMATION" at 314.503,161.447 h1.52
  text "MIN. TRACK WIDTH:" at 298.131,158.091 h1.52
  text "8" at 325.976,158.091 h1.52
  text "MIL" at 329.907,158.091 h1.52
  text "MIN. CLEARANCE:" at 298.131,154.938 h1.52
  text "0.2" at 324.452,154.938 h1.52
  text "mm" at 329.907,154.938 h1.52
  text "MIN. VIA PAD SIZE:" at 298.131,151.785 h1.52
  text "24" at 325.214,151.785 h1.52
  text "MIL" at 329.907,151.785 h1.52
  text "0.05mm (2MIL)" at 315.784,148.486 h1.52
  text "MINIMUM ANNULAR RING" at 289.769,148.277 h1.52
  text "EXTERNAL" at 333.768,148.277 h1.52
  text "PER" at 294.849,145.48 h1.52
  text "IPC-D-275 CLASS 2 LEVEL C" at 300.437,145.48 h1.52
  text "MIL, HOLES" at 338.238,142.928 h1.52
  text "+/-" at 328.27,142.709 h1.52
  text "+/-" at 349.961,142.709 h1.52
  text "REGISTRATION TOLERANCES:" at 289.769,142.682 h1.52
  text "METAL" at 320.243,142.682 h1.52
  text "5" at 334.879,142.683 h1.52
  text "3" at 356.037,142.683 h1.52
  text "MIL" at 358.99,142.682 h1.52
  text "HOLE SIZE TOLERANCE (UNLESS OTHERWISE SPECIFIED):" at 289.769,140.185 h1.52
  text "+/-" at 349.961,140.112 h1.52
  text "3" at 356.037,140.085 h1.52
  text "MIL" at 358.99,140.085 h1.52
  text "MATERIAL:" at 287.87,136.589 h1.52
  text "FR-4 High Tg" at 312.926,133.324 h1.52
  text "X" at 309.257,133.122 h1.52
  text "FR-408" at 298.563,133.007 h1.52
  text "OTHER" at 336.358,133.007 h1.52
  text "62 MIL (1.6mm) +/-10%" at 306.694,129.374 h1.52
  text "X" at 303.643,129.312 h1.52
  text "THICKNESS:" at 289.769,129.165 h1.52
  text "OTHER" at 339.33,129.165 h1.52
  text "TOLERANCE:" at 289.769,125.652 h1.52
  text "X" at 311.314,125.652 h1.52
  text "ANSI IPC-6012 TYPE 3 CLASS 2" at 315.836,125.652 h1.52
  text "OTHER +/-" at 315.835,121.989 h1.52
  text "BOW & TWIST:" at 289.769,118.302 h1.52
  text "X" at 311.314,118.302 h1.52
  text "ANSI IPC-6012 TYPE 3 CLASS 2" at 315.836,118.302 h1.52
  text "OTHER +/-" at 315.835,114.576 h1.52
  text "DRILLING:" at 287.87,111.258 h1.52
  text "NC_DRILL FILES" at 332.599,108.586 h1.52
  text "REFERENCE:" at 289.769,108.486 h1.52
  text "X" at 306.463,108.484 h1.52
  text "AS SHOWN" at 310.984,108.486 h1.52
  text "X" at 329.348,108.486 h1.52
  text "OTHER" at 340.168,104.873 h1.52
  text "PTH COPPER THICKNESS:" at 289.761,104.783 h1.52
  text "X" at 318.697,104.783 h1.52
  text "20-30 um" at 321.948,104.783 h1.52
  text "BOARD FINISH:" at 287.87,101.034 h1.52
  text "SILKSCREEN:" at 291.812,98.237 h1.52
  text "X" at 316.14,98.237 h1.52
  text "TOP" at 319.112,98.237 h1.52
  text "X" at 329.094,98.237 h1.52
  text "BOTTOM" at 332.091,98.237 h1.52
  text "SILKSCREEN COLOR:" at 291.812,94.295 h1.52
  text "X" at 316.115,94.295 h1.52
  text "WHITE" at 319.112,94.295 h1.52
  text "OTHER" at 332.091,94.295 h1.52
  text "X" at 319.442,90.652 h1.52
  text "GREEN" at 322.439,90.652 h1.52
  text "OTHER" at 338.136,90.652 h1.52
  text "SOLDER RESIST COLOR:" at 291.812,90.477 h1.52
  text "X" at 319.442,86.734 h1.52
  text "MATTE" at 322.439,86.734 h1.52
  text "SEMI-GLOSS" at 338.125,86.717 h1.52
  text "IMMERSION GOLD (ENIG)" at 314.819,82.345 h1.52
  text "ENEPIG" at 348.793,82.162 h1.52
  text "SURFACE FINISH:" at 287.87,82.136 h1.52
  text "X" at 310.298,82.136 h1.52
  text "IMM. TIN/SILVER OR EQUIV" at 296.24,78.649 h1.52
  text "OTHER" at 332.599,78.549 h1.52
  text "ARRAY/PANEL:" at 287.87,74.602 h1.52
  text "CUT AND TRIM PER M1 BOARD OUTLINE" at 314.819,74.393 h1.52
  text "N.C. ROUTE" at 314.819,70.94 h1.52
  text "X" at 332.295,70.94 h1.52
  text "V. SCORE" at 336.816,70.94 h1.52
  text "CERTIFICATION:" at 287.87,67.66 h1.52
  text "MATERIALS AND WORKMANSHIP FOR ALL PCBS" at 306.285,67.66 h1.52
  text "TO MEET OR EXCEED THE REQUIREMENTS OF:" at 306.285,65.271 h1.52
  text "X" at 297.078,62.003 h1.52
  text "ANSI IPC-A-600F CLASS ->" at 300.329,62.003 h1.52
  text "X" at 342.188,62.003 h1.52
  text "2" at 344.982,62.003 h1.52
  text "1" at 336.981,61.965 h1.52
  text "3" at 353.973,61.965 h1.52
  text "X" at 317.702,58.252 h1.52
  text "RoHS" at 320.953,58.252 h1.52
  text "OTHER" at 337.321,58.252 h1.52
  text "PER ORDER" at 347.407,58.252 h1.52
  text "ALL BOARDS MUST MEET OR EXCEED UL94-V0 REQUIREMENTS." at 288.569,54.345 h1.52
  text "PCB MUST BEAR THE UL94V-0 UL REGISTERED MATERIAL ID NUMBER" at 288.569,51.397 h1.52
  text "ADDITIONAL REQUIREMENTS:" at 287.87,47.094 h1.52
  text "MICROSECTION:" at 289.769,44.373 h1.52
  text "YES" at 312.775,44.373 h1.52
  text "REQUIRED" at 334.657,40.707 h1.52
  text "BARE BOARD ELEC. TEST:" at 289.769,40.634 h1.52
  text "NONE" at 322.935,40.634 h1.52
  text "X" at 331.66,40.634 h1.52
  text "PER ORDER" at 349.693,40.634 h1.52
  text "XX MIL VIAS REQUIRE NON-CONDUCTIVE FILL AND PLANARIZE" at 294.04,35.428 h1.5
  text "XX MIL VIAS REQUIRE CONDUCTIVE FILL AND PLANARIZE" at 294.243,32.787 h1.52
  text "OUTER XX MIL TRACES REQUIRE 50 OHM SINGLE-ENDED IMPEDANCE" at 294.218,28.637 h1.47
  text "LAYER 2 & 3 (INNER LAYERS) XX MIL WIDE, XX MIL SPACE / TRACES REQUIRE 100 OHM DIFFERENTIAL IMPEDANCE" at 294.015,22.65 h1.52
  text ".Layer_Name" at 14.656,-21.806 h1.52
M11 Gerber Information:
  lines w0.254: -7.417,-23.626 160.223,-23.626 ; -7.417,-18.462 160.274,-18.462 ; -7.417,-13.297 -7.417,-28.791 94.31,-28.791 160.274,-28.791 160.274,-13.297 -7.404,-13.297 -7.404,-28.791 32.614,-28.791 ; 55.194,-28.791 55.194,-13.297 ; 87.376,-18.462 87.376,-13.297 ; 108.712,-18.462 108.712,-13.297 ; 124.511,-28.956 124.511,-23.804
  text "ALL ARTWORK VIEWED FROM TOP SIDE" at -5.804,-16.654 h1.52
  text "BOARD #:" at 57.099,-16.654 h1.52
  text ".PRJ_Number" at 70.955,-16.654 h1.52
  text "REV:" at 92.405,-16.654 h1.52
  text ".PCB_Rev" at 99.809,-16.654 h1.52
  text "SVN REV:" at 113.69,-16.654 h1.52
  text ".VersionControl_RevNumber" at 126.543,-16.654 h1.52
  text "LAYER NAME =" at -5.804,-21.806 h1.52
  text "TID #:" at 57.099,-21.819 h1.52
  text ".TID" at 70.955,-21.819 h1.52
  text "PLOT NAME =" at -5.804,-27.034 h1.52
  text ".plot_File_Name" at 14.656,-27.034 h1.52
  text "GENERATED    :" at 57.15,-27.034 h1.52
  text ".Print_Date" at 79.235,-27.034 h1.52
  text ".Print_Time" at 97.752,-27.034 h1.52
  text "TEXAS INSTRUMENTS" at 129.87,-27.034 h1.52
M12 Stackup:
  drawing of 295 lines, arcs and shapes, not listed
  text "Layer" at 249.119,199.453 h1.52
  text "Name" at 259.531,199.453 h1.52
  text "Material" at 283.147,199.453 h1.52
  text "Thickness" at 304.985,199.453 h1.52
  text "Constant" at 321.49,199.453 h1.52
  text "Board Layer Stack" at 335.965,199.453 h1.52
  text "Top Overlay" at 259.531,196.405 h1.52
  text "Top Solder" at 259.531,193.357 h1.52
  text "Solder Resist" at 283.147,193.357 h1.52
  text "0.40mil" at 304.985,193.357 h1.52
  text "3.5" at 321.49,193.357 h1.52
  text "1" at 249.119,190.309 h1.52
  text "Top Layer" at 259.531,190.309 h1.52
  text "1.40mil" at 304.985,190.309 h1.52
  text "Dielectric 1" at 259.531,187.261 h1.52
  text "PP-006" at 283.147,187.261 h1.52
  text "2.80mil" at 304.985,187.261 h1.52
  text "4.1" at 321.49,187.261 h1.52
  text "2" at 249.119,184.213 h1.52
  text "Layer 1" at 259.531,184.213 h1.52
  text "CF-004" at 283.147,184.213 h1.52
  text "1.38mil" at 304.985,184.213 h1.52
  text "Dielectric1" at 259.531,181.165 h1.52
  text "FR-4" at 283.147,181.165 h1.52
  text "59.20mil" at 304.985,181.165 h1.52
  text "4.8" at 321.49,181.165 h1.52
  text "3" at 249.119,178.118 h1.52
  text "Layer 2" at 259.531,178.118 h1.52
  text "CF-004" at 283.147,178.118 h1.52
  text "1.38mil" at 304.985,178.118 h1.52
  text "Dielectric 2" at 259.531,175.07 h1.52
  text "PP-006" at 283.147,175.07 h1.52
  text "2.80mil" at 304.985,175.07 h1.52
  text "4.1" at 321.49,175.07 h1.52
  text "4" at 249.119,172.022 h1.52
  text "Bottom Layer" at 259.531,172.022 h1.52
  text "1.40mil" at 304.985,172.022 h1.52
  text "Bottom Solder" at 259.531,168.974 h1.52
  text "Solder Resist" at 283.147,168.974 h1.52
  text "0.40mil" at 304.985,168.974 h1.52
  text "3.5" at 321.49,168.974 h1.52
  text "Bottom Overlay" at 259.531,165.925 h1.52
  text ".Layer_Name" at 14.656,-21.806 h1.52
M13 Component Bodies Top:
  text ".Layer_Name" at 14.656,-21.806 h1.52
M14 Component Bodies Bottom:
  text ".Layer_Name" at 14.656,-21.806 h1.52
M15 Courtyards Top:
  text ".Layer_Name" at 14.656,-21.806 h1.52
M16 Courtyards Bottom:
  text ".Layer_Name" at 14.656,-21.806 h1.52
Drill Drawing:
  lines w0.254: 135.538,72.615 136.944,72.615 136.944,74.02 135.538,74.02 135.538,72.615 ; 135.538,77.183 136.944,77.183 136.241,75.777 135.538,77.183 ; 135.538,79.291 135.89,79.291 136.241,78.939 136.593,79.291 136.944,79.291 136.593,79.642 136.944,79.993 136.593,79.993 136.241,80.345 135.89,79.993 135.538,79.993 135.89,79.642 135.538,79.291 ; 135.538,82.102 136.241,82.453 136.944,82.102 136.593,82.804 136.944,83.507 136.241,83.156 135.538,83.507 135.89,82.804 135.538,82.102
  lines w0.305: 134.264,71.666 216.362,71.666 ; 134.264,84.315 216.362,84.315 ; 142.85,68.504 142.85,87.478 ; 151.287,68.504 151.287,87.478 ; 167.453,68.504 167.453,87.478 ; 174.037,68.504 174.037,87.478 ; 183.568,68.504 183.568,87.478 ; 201.972,68.504 201.972,87.478 ; 134.264,68.504 216.362,68.504 216.362,87.478 134.264,87.478 134.264,68.504
  text "Symbol" at 136.162,85.264 h1.83
  text "Quantity" at 143.799,85.264 h1.83
  text "Finished Hole Size" at 152.235,85.264 h1.83
  text "Plated" at 168.402,85.264 h1.83
  text "Hole Type" at 174.986,85.264 h1.83
  text "Drill Layer Pair" at 184.517,85.264 h1.83
  text "Hole Tolerance" at 202.92,85.264 h1.83
  text "4" at 143.799,82.102 h1.52
  text "11.81mil (0.300mm)" at 152.235,82.102 h1.52
  text "PTH" at 168.402,82.102 h1.52
  text "Round" at 174.986,82.102 h1.52
  text "Top Layer - Bottom Layer" at 184.517,82.102 h1.52
  text "30" at 143.799,78.939 h1.52
  text "12.00mil (0.305mm)" at 152.235,78.939 h1.52
  text "PTH" at 168.402,78.939 h1.52
  text "Round" at 174.986,78.939 h1.52
  text "Top Layer - Bottom Layer" at 184.517,78.939 h1.52
  text "6" at 143.799,75.777 h1.52
  text "16.00mil (0.406mm)" at 152.235,75.777 h1.52
  text "PTH" at 168.402,75.777 h1.52
  text "Round" at 174.986,75.777 h1.52
  text "Top Layer - Bottom Layer" at 184.517,75.777 h1.52
  text "6" at 143.799,72.615 h1.52
  text "40.00mil (1.016mm)" at 152.235,72.615 h1.52
  text "PTH" at 168.402,72.615 h1.52
  text "Round" at 174.986,72.615 h1.52
  text "Top Layer - Bottom Layer" at 184.517,72.615 h1.52
  text "46 Total" at 143.799,69.452 h1.52
  text ".Layer_Name" at 14.656,-21.806 h1.52
M17 Embedded Cavity:
  text ".Layer_Name" at 14.656,-21.806 h1.52
M18 Embedded Assembly:
  text ".Layer_Name" at 14.656,-21.806 h1.52
M19 Embedded Keepout:
  text ".Layer_Name" at 14.656,-21.806 h1.52

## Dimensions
0,-10.16 to 25.4,-10.16 on M2 Board Dimensions
0,0 to 0,19.685 on M2 Board Dimensions
0,0 to 38.735,0 on M2 Board Dimensions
